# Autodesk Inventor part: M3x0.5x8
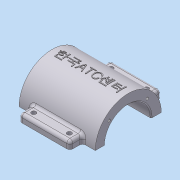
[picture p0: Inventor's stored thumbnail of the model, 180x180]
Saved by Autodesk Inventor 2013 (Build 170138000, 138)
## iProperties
Company: 한국ATC센터
Created: 2009-02
Part Number: M3x0.5x8
Document SubType Name: Modeling
Designer: KYOUNG IL JANG
Density: 2.71 g/cm^3
Mass: 199.244 g
Surface Area: 195.42 cm^2
Volume: 73.5218 cm^3
Material: 알루미늄-6061
Vendor: CBT Solutions
Author: KYOUNG IL JANG
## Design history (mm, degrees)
sketch "스케치1"
  geometry: L1 (-45, 40)-(45, 40); L2 (45, 40)-(45, -40); L3 (45, -40)-(-45, -40); L4 (-45, -40)-(-45, 40); 3 further points
  constraints: 8 end point, 2 midpoint, 2 parallel, 1 horizontal, 1 horizontal alignment, 1 perpendicular, 1 vertical alignment
  dimensions: "d0" = 90 distance of L2.end L3.end; "d1" = 80 distance of L1.end L2.end
extrude "돌출1" new body sketch "스케치1" distance "d2" = 10; taper "d3" = 0 deg
sketch "스케치2"
  geometry: L1 (40, 0)-(-40, 0) reference; C1 r 32.5 at (0, 80); 2 further points
  constraints: 1 centre point, 1 midpoint, 1 vertical alignment
  dimensions: "d4" = 65 diameter of C1; "d5" = 80 distance from line of C1.centre L1
extrude "돌출2" join sketch "스케치2" stored distance "d6" = 75; taper "d7" = 0 deg
sketch "스케치3"
  geometry: L1 (-7.5, -20)-(7.5, -20); L2 (7.5, 20)-(-7.5, 20); A1 r 20 centre (7.5, 0) between (7.5, -20) and (7.5, 20); A2 r 20 centre (-7.5, 0) between (-7.5, 20) and (-7.5, -20); 2 further points
  constraints: 4 end point, 4 point on circle, 4 tangent, 2 centre point, 1 horizontal, 1 horizontal alignment, 1 midpoint, 1 parallel, 1 vertical alignment
  dimensions: "d8" = 20 radius of A2; "d9" = 55 dimension on A1 A2
extrude "돌출3" join sketch "스케치3" stored distance "d10" = 75; taper "d11" = 0 deg
fillet "모깎기1" dims "d12" = 10
sketch "스케치4"
  geometry: L1 (-45, 0)-(-45, 10) reference; L2 (37.5, 47.5)-(-37.5, 47.5) reference; L3 (-45, 10)-(-27.513, 47.5); 1 further point
  constraints: 2 end point, 1 point on line
  dimensions: "d13" = 25 deg angle of L3 L1
sketch "스케치5"
  geometry: L1 (-40, 0)-(-40, 10) reference; L2 (-40, 10)-(-22.912, 56.95); 2 further points
  constraints: 2 end point, 2 other
  dimensions: "d14" = 20 deg angle of L2 L1
feature "리브1" dims "d15" = 1, "d16" = 6, "d17" = 0
feature "리브2" dims "d18" = 1, "d19" = 6, "d20" = 0
fillet "모깎기2" dims "d21" = 3
fillet "모깎기3" dims "d22" = 3
fillet "모깎기4" dims "d23" = 3
fillet "모깎기5" dims "d24" = 3
fillet "모깎기6" dims "d25" = 3
fillet "모깎기7" dims "d26" = 3
fillet "모깎기8" dims "d27" = 3
sketch "스케치6"
  geometry: A1 r 10 centre (35, -30) between (35, -40) and (45, -30) reference; 1 further point
hole "구멍1" sketch "스케치6" at (35, -30) diameter "d28" = 10; stored, may be unused: countersink angle "d32" = 90 deg, drill point angle "d34" = 118 deg; dims "d29" = 6, "d30" = 4, "d31" = 2, "d33" = 8
hole "구멍2" diameter "d37" = 45; stored, may be unused: countersink angle "d41" = 90 deg, drill point angle "d43" = 118 deg; dims "d35" = 10, "d36" = 10, "d38" = 6, "d39" = 4, "d40" = 2, "d42" = 8
sketch "스케치7"
  geometry: C1 r 22.5 at (0, 0) reference; 2 further points
  dimensions: "d44" = 135 deg dimension on C1.centre point (-18.738, 18.738) point (80, 0); "d45" = 26.5 distance of point (-18.738, 18.738) C1.centre
hole "구멍3" sketch "스케치7" at (-18.738, 18.738) diameter "d46" = 2.459; stored, may be unused: countersink angle "d50" = 90 deg, drill point angle "d52" = 118 deg; dims "d47" = 8, "d48" = 4, "d49" = 2, "d51" = 10
node "작업 평면1"
chamfer "모따기1" distance "d69" = 1; stored, may be unused: second distance "d70" = 2, angle "d71" = 45 deg
sketch "스케치9"
  geometry: L1 (-31.623, 87.5)-(-45, 87.5); L2 (-45, 87.5)-(-45, 72.5); L3 (-45, 72.5)-(-31.623, 72.5); A1 r 32.5 centre (0, 80) between (-31.623, 87.5) and (-31.623, 72.5) reference; 1 further point
  constraints: 6 end point, 2 parallel, 2 point on circle, 1 horizontal, 1 perpendicular
  dimensions: "d73" = 15 distance of L1.end L2.end; "d74" = 45 distance from line of A1.centre L2
extrude "돌출5" join sketch "스케치9" stored distance "d75" = 50; taper "d76" = 0 deg
fillet "모깎기10" dims "d77" = 3
fillet "모깎기11" dims "d78" = 3
sketch "스케치10"
  geometry: L1 (100.378, 66.389)-(0, 66.389); L2 (0, 66.389)-(0, -76.978); L3 (0, -76.978)-(100.378, -76.978); L4 (100.378, -76.978)-(100.378, 66.389); C1 r 32.5 at (0, 0) reference; 1 further point
  constraints: 8 end point, 2 parallel, 1 horizontal, 1 perpendicular, 1 point on line
extrude "돌출6" cut sketch "스케치10" stored distance "d79" = 10; taper "d80" = 0 deg
sketch "스케치11"
  geometry: C1 r 1.621 at (4.5, 4) reference; C2 r 1.621 at (39.5, 4) reference; 1 further point
hole "구멍5" sketch "스케치11" at (39.5, 4), (4.5, 4) diameter "d81" = 4.5; stored, may be unused: countersink angle "d85" = 90 deg, drill point angle "d87" = 118 deg; dims "d82" = 6, "d83" = 4, "d84" = 2, "d86" = 8
node "작업 평면2"
sketch "스케치12"
  geometry: 2 further points
  constraints: 1 coincident, 1 other
feature "엠보싱1" sketch "스케치12" dims "d8" = 20, "d9" = 55, "d88" = 0.5, "d89" = 0
node "솔리드1"
mirror "대칭1"
mirror "대칭2"
mirror "대칭3"
mirror "대칭4"
pattern_circular "원형 패턴1" dims angle "d54" = 360 deg
mirror "대칭5"
mirror "대칭6"
mirror "대칭7"
node "참조1"
node "참조2"
other parameters: "d56" = -117
